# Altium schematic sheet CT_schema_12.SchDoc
size 741 x 377 mm
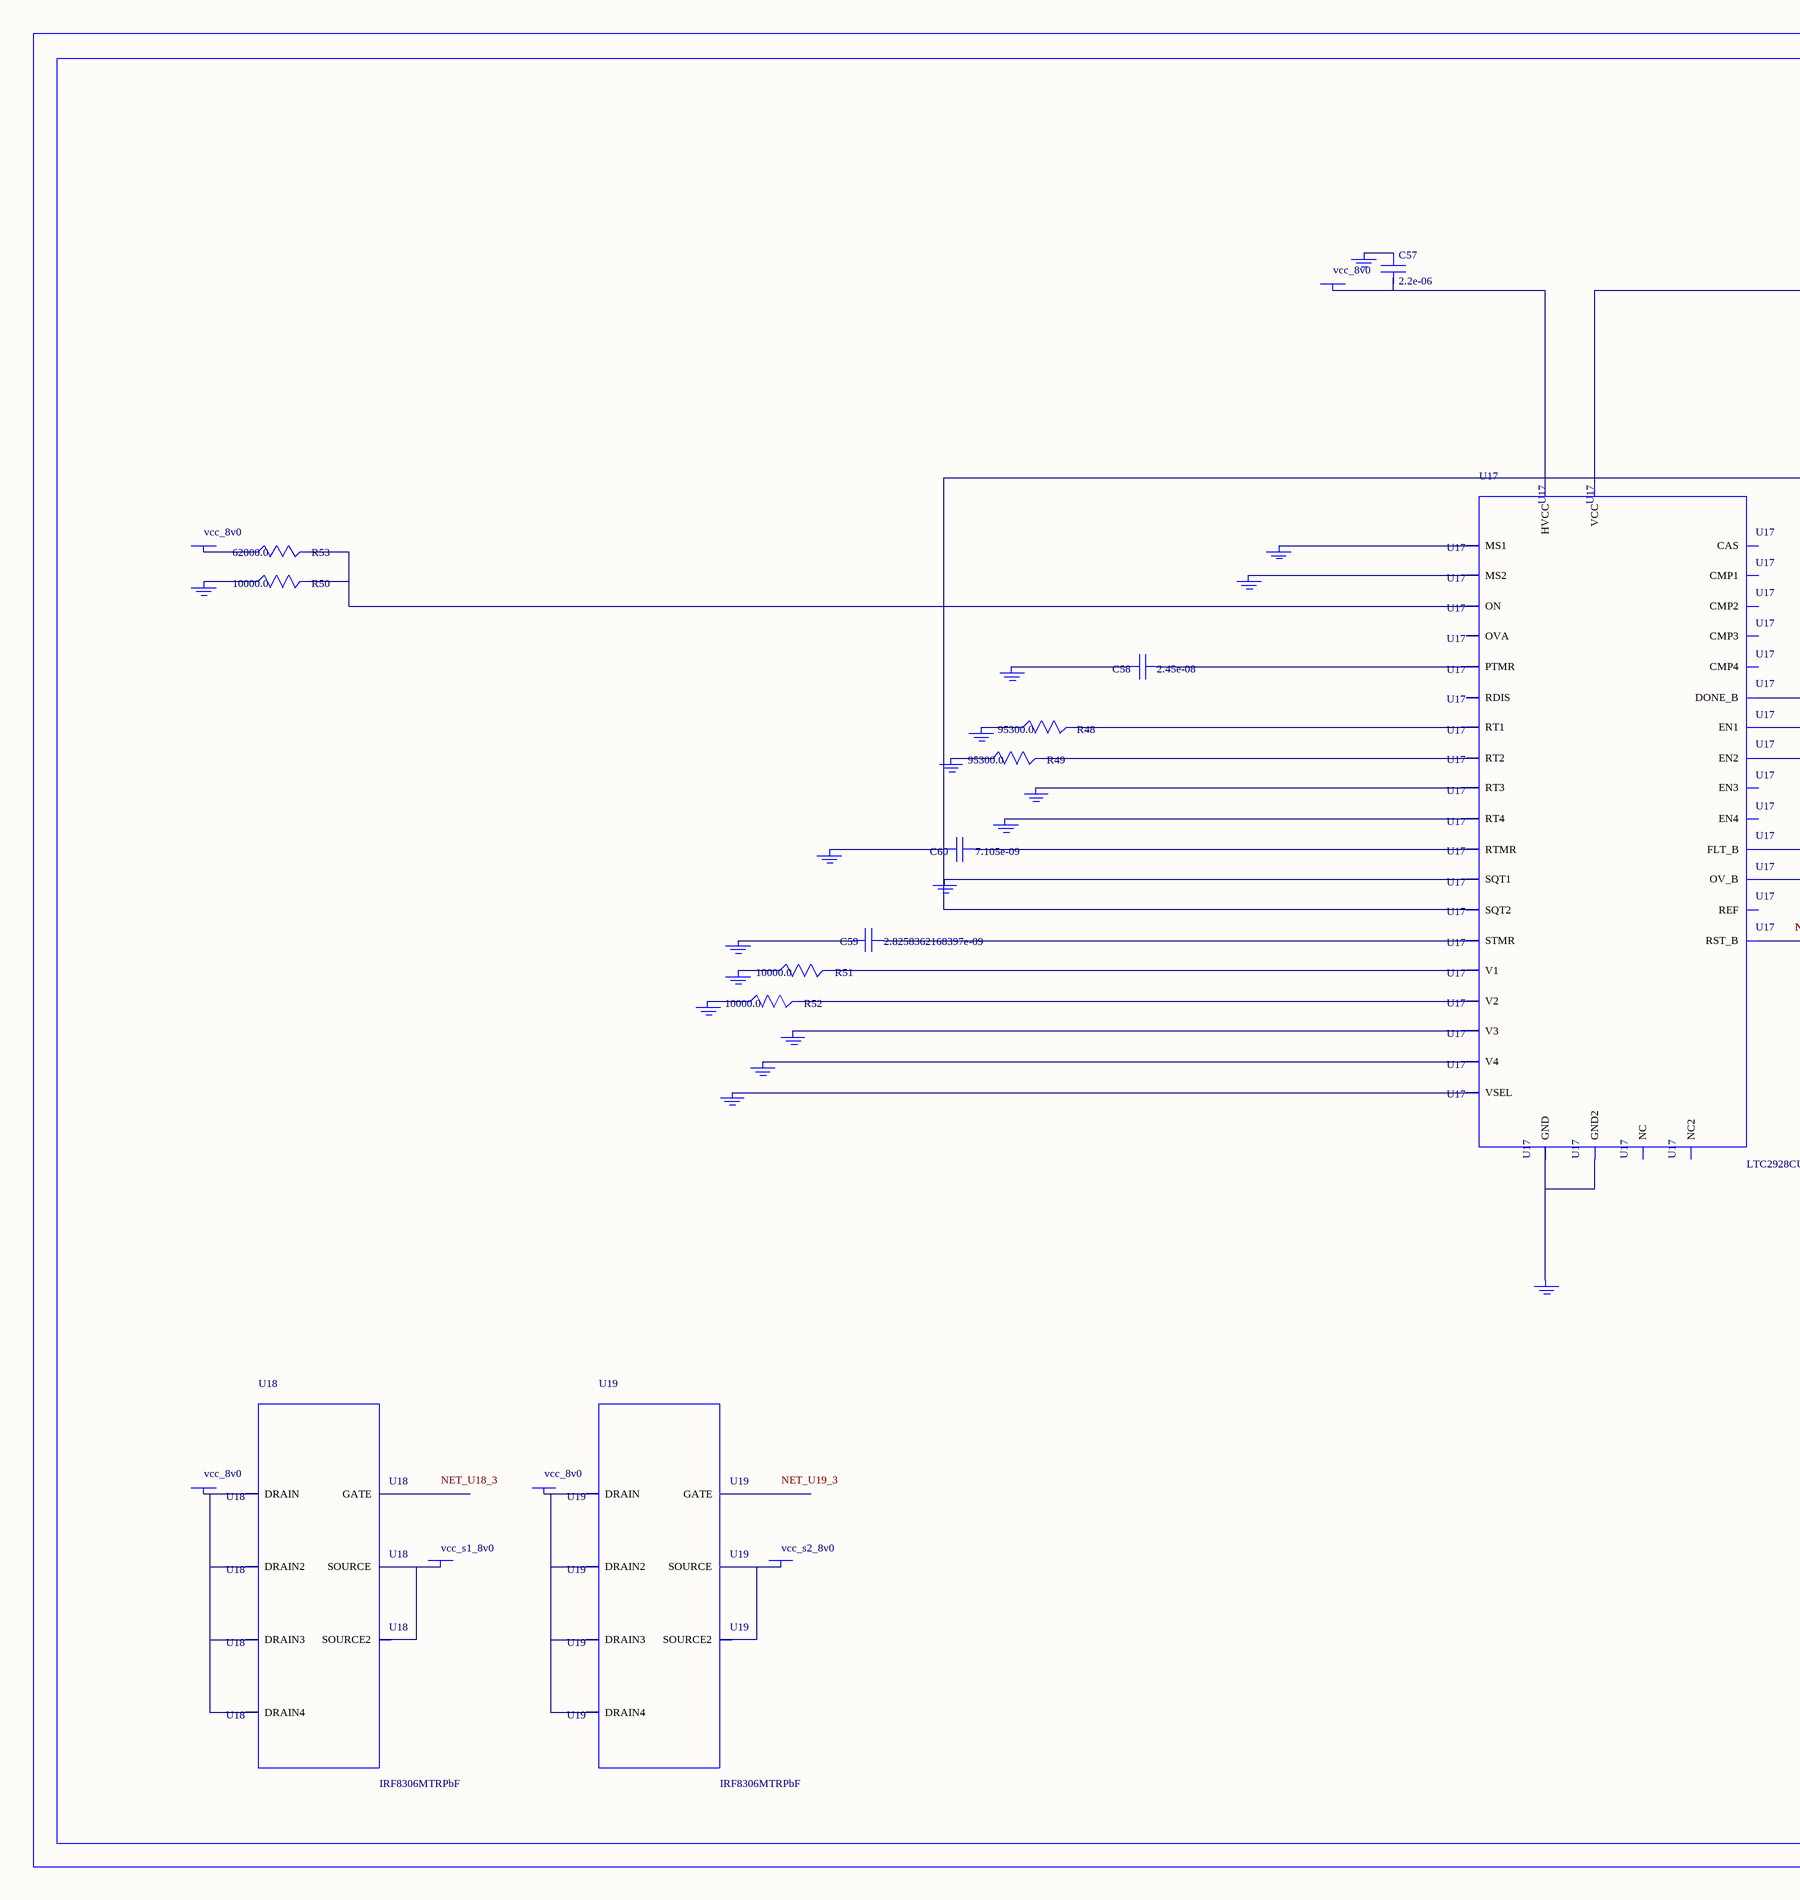
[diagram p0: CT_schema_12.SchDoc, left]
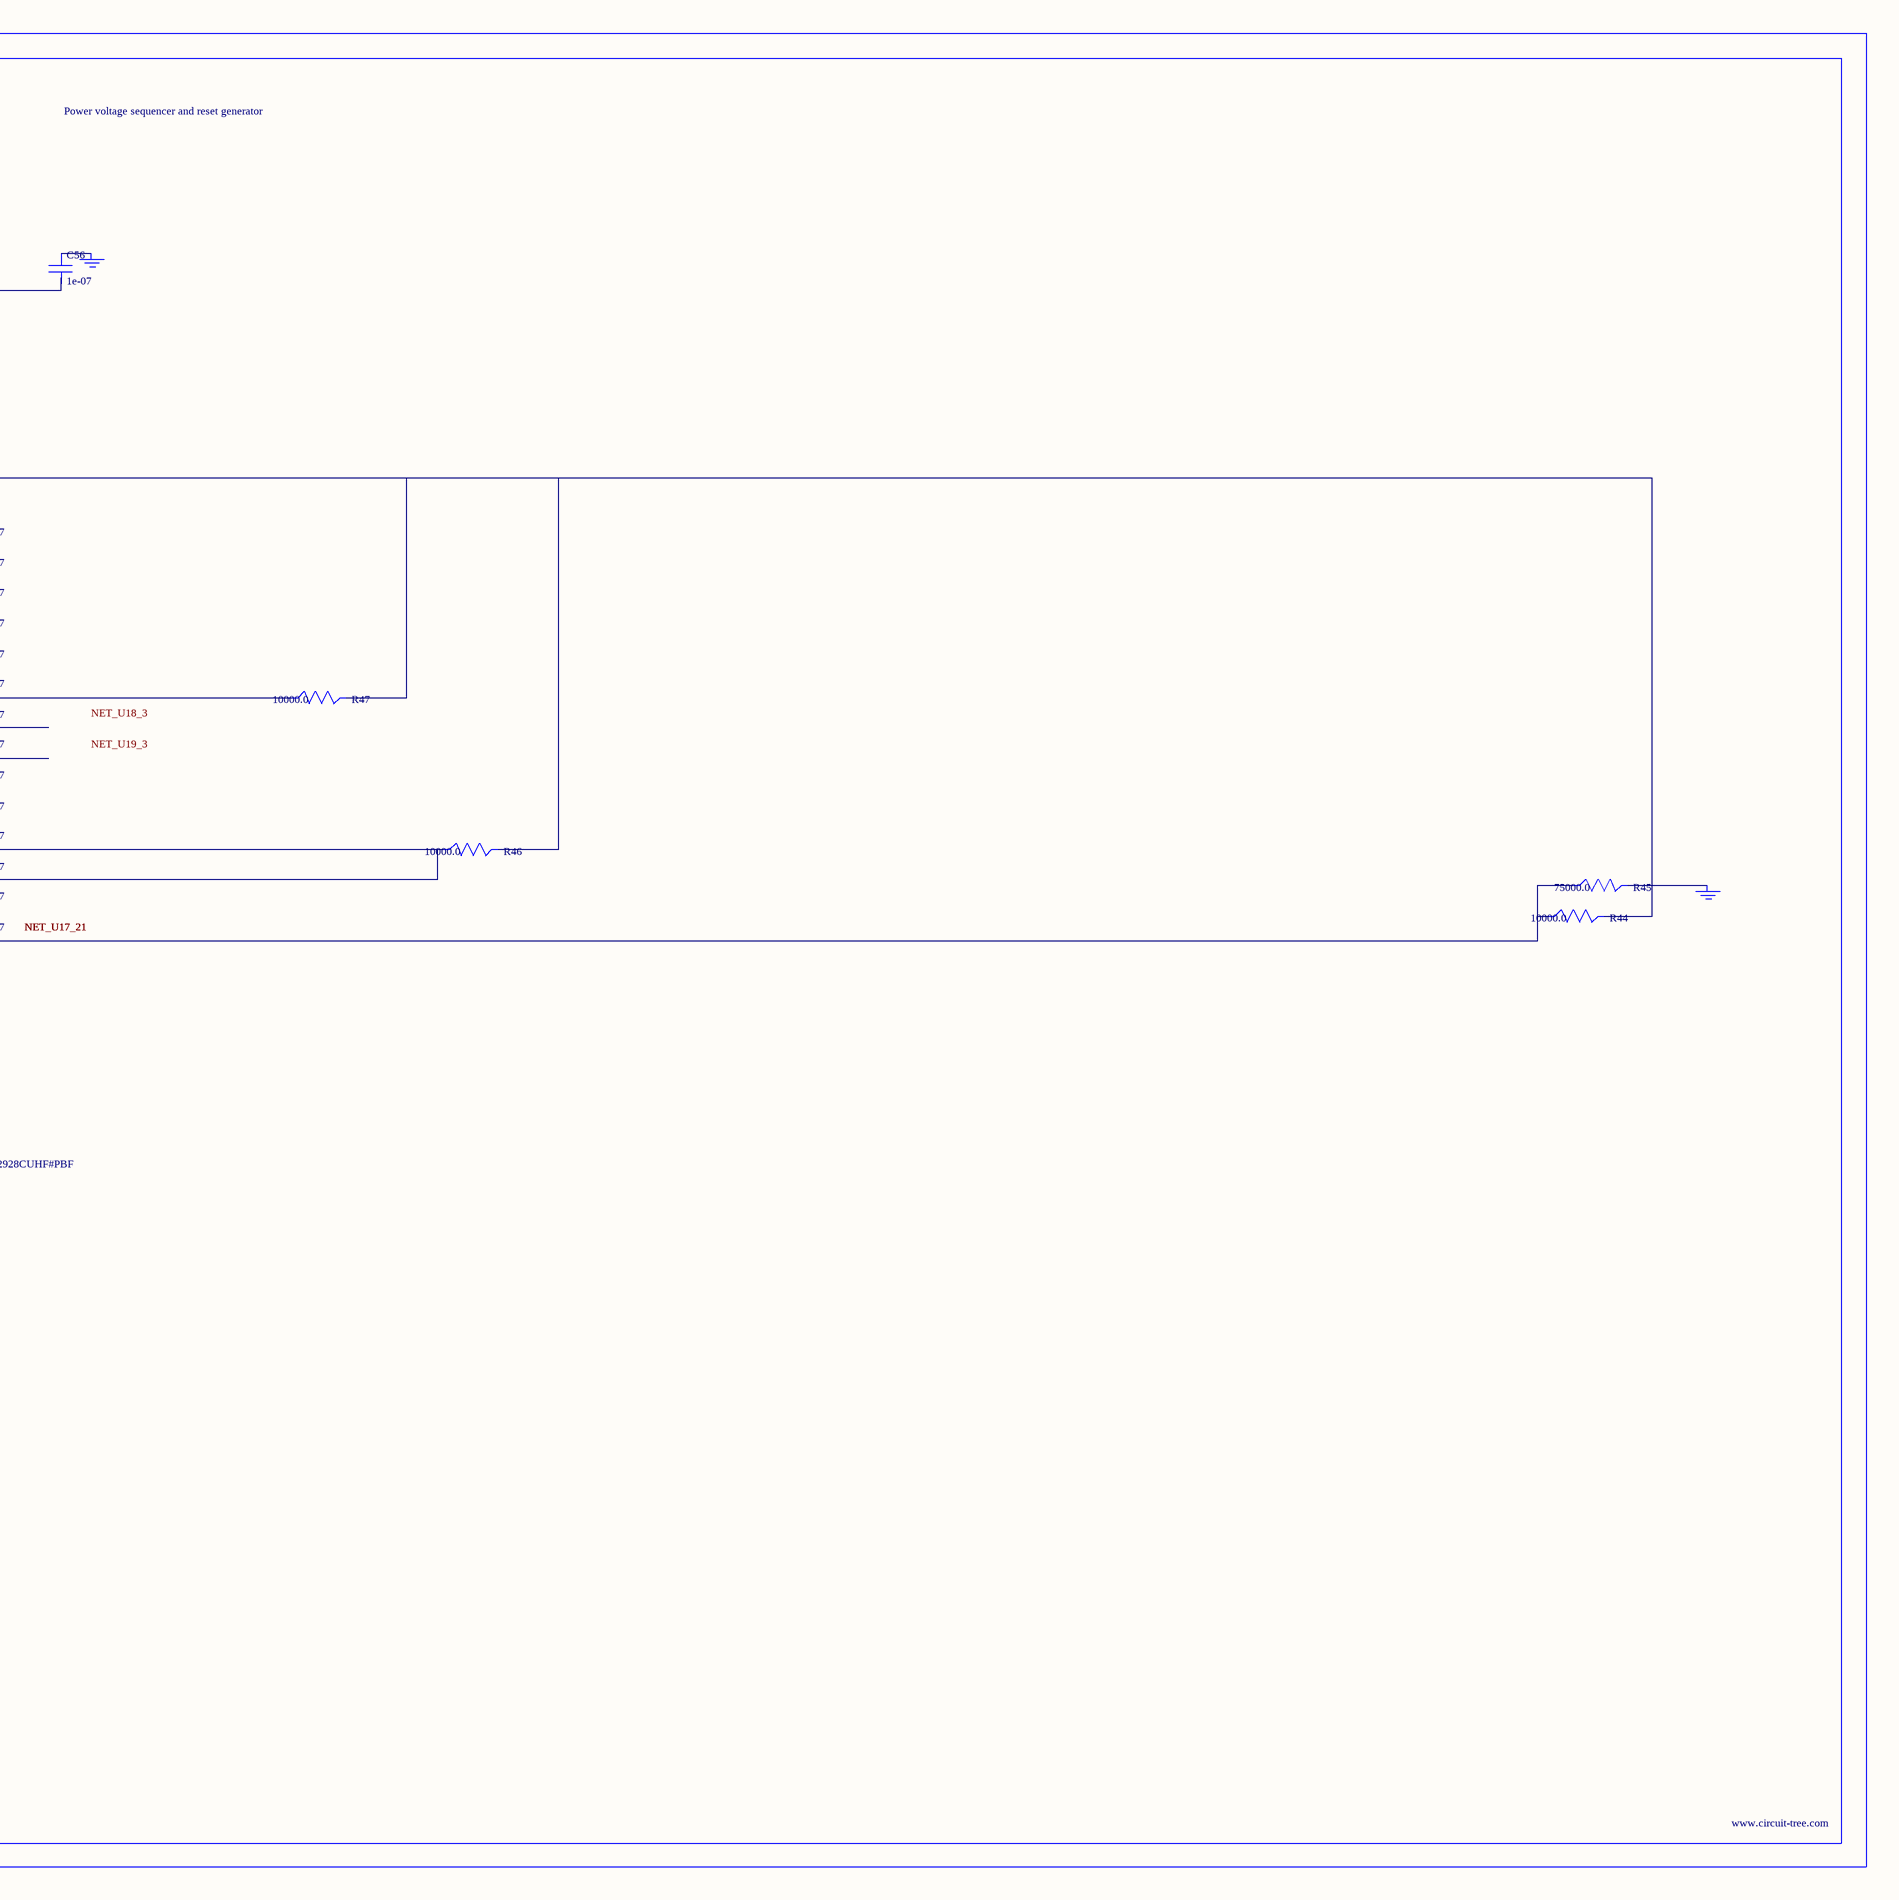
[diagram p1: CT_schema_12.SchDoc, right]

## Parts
BORDER11  (no value)
C56  1e-07  [C0402]
C57  2.2e-06  [C0603]
C58  2.45e-08  [R0603]
C59  2.8258362168397e-09  [R0603]
C60  7.105e-09  [R0603]
GND_INSTANCE_11_0  (no value)
GND_INSTANCE_11_1  (no value)
GND_INSTANCE_11_2  (no value)
GND_INSTANCE_11_3  (no value)
GND_INSTANCE_11_4  (no value)
GND_INSTANCE_11_5  (no value)
GND_INSTANCE_11_6  (no value)
GND_INSTANCE_11_7  (no value)
GND_INSTANCE_11_8  (no value)
GND_INSTANCE_11_9  (no value)
GND_INSTANCE_11_10  (no value)
GND_INSTANCE_11_11  (no value)
GND_INSTANCE_11_12  (no value)
GND_INSTANCE_11_13  (no value)
GND_INSTANCE_11_14  (no value)
GND_INSTANCE_11_15  (no value)
GND_INSTANCE_11_16  (no value)
GND_INSTANCE_11_17  (no value)
GND_INSTANCE_11_18  (no value)
GND_INSTANCE_11_19  (no value)
POWER_INSTANCE_11_0  vcc_8v0
POWER_INSTANCE_11_1  vcc_8v0
POWER_INSTANCE_11_2  vcc_8v0
POWER_INSTANCE_11_3  vcc_s1_8v0
POWER_INSTANCE_11_4  vcc_8v0
POWER_INSTANCE_11_5  vcc_s2_8v0
R44  10000.0  [R0603]
R45  75000.0  [R0603]
R46  10000.0  [R0603]
R47  10000.0  [R0603]
R48  95300.0  [R0603]
R49  95300.0  [R0603]
R50  10000.0  [R0603]
R51  10000.0  [R0603]
R52  10000.0  [R0603]
R53  62000.0  [R0603]
U17  LTC2928CUHF#PBF  [QFN-38_UHF]
U18  IRF8306MTRPbF  [IRF8306MTRPBF]
U19  IRF8306MTRPbF  [IRF8306MTRPBF]

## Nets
NetC56_1: C56.1 GND_INSTANCE_11_10.0(GND)
NetC56_2: C56.2 C60.2 GND_INSTANCE_11_5.0(GND) GND_INSTANCE_11_15.0(GND) R44.2 R46.2 R47.2 U17.10(SQT1) U17.11(SQT2) U17.22(VCC)
NetC57_1: C57.1 GND_INSTANCE_11_11.0(GND)
NetC57_2: C57.2 POWER_INSTANCE_11_1.0(PWR) U17.23(HVCC)
NetC58_1: C58.1 U17.27(PTMR)
NetC58_2: C58.2 GND_INSTANCE_11_14.0(GND)
NetC59_1: C59.1 U17.26(STMR)
NetC59_2: C59.2 GND_INSTANCE_11_13.0(GND)
NetC60_1: C60.1 U17.28(RTMR)
NetGND_INSTANCE_11_0_0: GND_INSTANCE_11_0.0(GND) R51.1
NetGND_INSTANCE_11_1_0: GND_INSTANCE_11_1.0(GND) R48.1
NetGND_INSTANCE_11_2_0: GND_INSTANCE_11_2.0(GND) R49.1
NetGND_INSTANCE_11_3_0: GND_INSTANCE_11_3.0(GND) U17.8(RT3)
NetGND_INSTANCE_11_4_0: GND_INSTANCE_11_4.0(GND) U17.9(RT4)
NetGND_INSTANCE_11_6_0: GND_INSTANCE_11_6.0(GND) U17.12(MS1)
NetGND_INSTANCE_11_7_0: GND_INSTANCE_11_7.0(GND) U17.13(MS2)
NetGND_INSTANCE_11_8_0: GND_INSTANCE_11_8.0(GND) R50.1
NetGND_INSTANCE_11_9_0: GND_INSTANCE_11_9.0(GND) R45.2
NetGND_INSTANCE_11_12_0: GND_INSTANCE_11_12.0(GND) U17.25(VSEL)
NetGND_INSTANCE_11_16_0: GND_INSTANCE_11_16.0(GND) U17.30(V4)
NetGND_INSTANCE_11_17_0: GND_INSTANCE_11_17.0(GND) U17.32(V3)
NetGND_INSTANCE_11_18_0: GND_INSTANCE_11_18.0(GND) R52.1
NetGND_INSTANCE_11_19_0: GND_INSTANCE_11_19.0(GND) U17.24(GND) U17.39(GND2)
NetPOWER_INSTANCE_11_0_0: POWER_INSTANCE_11_0.0(PWR) R53.1
NetPOWER_INSTANCE_11_2_0: POWER_INSTANCE_11_2.0(PWR) U18.1(DRAIN) U18.2(DRAIN2) U18.6(DRAIN3) U18.7(DRAIN4)
NetPOWER_INSTANCE_11_3_0: POWER_INSTANCE_11_3.0(PWR) U18.4(SOURCE) U18.5(SOURCE2)
NetPOWER_INSTANCE_11_4_0: POWER_INSTANCE_11_4.0(PWR) U19.1(DRAIN) U19.2(DRAIN2) U19.6(DRAIN3) U19.7(DRAIN4)
NetPOWER_INSTANCE_11_5_0: POWER_INSTANCE_11_5.0(PWR) U19.4(SOURCE) U19.5(SOURCE2)
NetR44_1: R44.1 R45.1 U17.21(RST_B)
NetR46_1: R46.1 U17.19(FLT_B) U17.20(OV_B)
NetR47_1: R47.1 U17.18(DONE_B)
NetR48_2: R48.2 U17.6(RT1)
NetR49_2: R49.2 U17.7(RT2)
NetR50_2: R50.2 R53.2 U17.16(ON)
NetR51_2: R51.2 U17.3(V1)
NetR52_2: R52.2 U17.38(V2)

Not connected (* = marked no-connect by the designer): U17 1(OVA) 2(EN1) 4(NC) 5(REF) 14(RDIS) 15(CAS) 17(NC2) 29(EN4) 31(EN3) 33(CMP3) 34(CMP4) 35(CMP1) 36(CMP2) 37(EN2); U18 3(GATE); U19 3(GATE)

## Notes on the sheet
- Labels drawn without touching a wire or pin: NET_U18_3, NET_U19_3

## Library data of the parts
BORDER11 = BORDER_PAGE11
C56 = C0402C104K3RACTU
C57 = GRM188R61H225KE1115D
C58 = C58
C59 = C59
C60 = C60
GND_INSTANCE_11_0-GND_INSTANCE_11_19 = GND
POWER_INSTANCE_11_0-POWER_INSTANCE_11_5 = PWR
R44 R46 R47 R50-R52 = RC0603JR-0710KL
R45 = RC0603JR-0775KL
R48 R49 = RC0603FR-0795K3L
R53 = RC0603JR-0762KL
